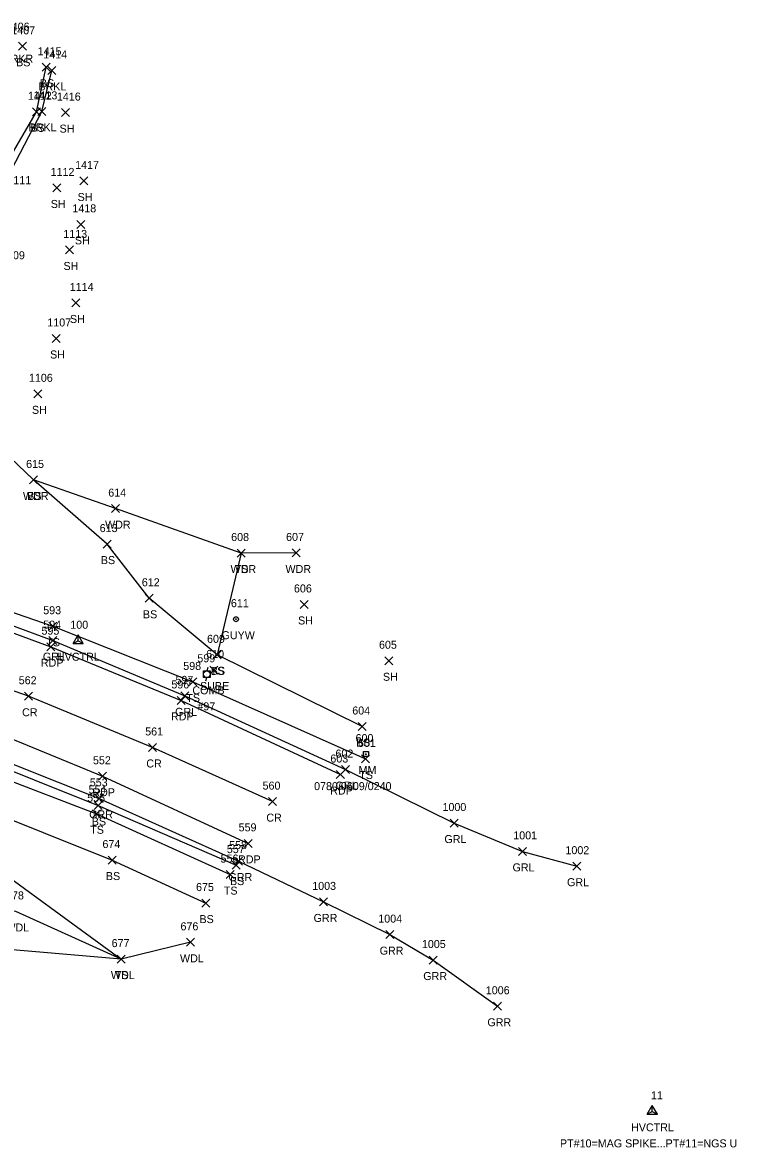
# Model space of a CAD drawing. Extents: x 1485624 to 1495982, y 886445 to 890805.
# Drawn here: x 1495803.4 to 1495981.7, y 890451.8 to 890732.9 of the extents above; entities that cross this region are included whole.
import ezdxf

# ---------------------------------------------------------------- set-up
doc = ezdxf.new("R2010")
doc.units = 0
for name, color, linetype in [('C_A', 7, 'Continuous'), ('C_C', 7, 'Continuous'), ('C_I', 7, 'Continuous'), ('CPSM', 7, 'Continuous'), ('L_A', 7, 'Continuous'), ('L_I', 7, 'Continuous'), ('L_TIC', 7, 'Continuous'), ('LAWA', 7, 'Continuous'), ('LAWE', 7, 'Continuous'), ('LELB', 7, 'Continuous'), ('P_A', 7, 'Continuous'), ('P_I', 7, 'Continuous'), ('P_TIC', 7, 'Continuous'), ('PET', 7, 'Continuous'), ('PRC', 7, 'Continuous'), ('R_A', 7, 'Continuous'), ('R_I', 7, 'Continuous'), ('R_TIC', 7, 'Continuous'), ('RGR', 7, 'Continuous'), ('S_A', 7, 'Continuous'), ('S_C', 7, 'Continuous'), ('S_I', 7, 'Continuous'), ('SRM', 7, 'Continuous'), ('U_A', 7, 'Continuous'), ('U_C', 7, 'Continuous'), ('U_I', 7, 'Continuous'), ('U_TIC', 7, 'Continuous'), ('UP', 7, 'Continuous'), ('UPGW', 7, 'Continuous')]:
    doc.layers.add(name, color=color, linetype=linetype)

msp = doc.modelspace()

# ---------------------------------------------------------------- linework, layer by layer
at = {"layer": 'CPSM'}
for p, q in [((1495816.06, 890577.72), (1495817.31, 890579.88)), ((1495816.06, 890577.72), (1495817.31, 890578.44)), ((1495816.06, 890577.72), (1495818.56, 890577.72)), ((1495818.56, 890577.72), (1495817.31, 890579.88)), ((1495817.31, 890578.44), (1495817.31, 890579.88)), ((1495817.31, 890578.44), (1495817.31, 890578.44)), ((1495817.31, 890578.44), (1495818.56, 890577.72)), ((1495959.45, 890460.14), (1495960.7, 890462.31)), ((1495961.95, 890460.14), (1495960.7, 890462.31)), ((1495960.7, 890460.87), (1495960.7, 890462.31)), ((1495959.45, 890460.14), (1495960.7, 890460.87)), ((1495959.45, 890460.14), (1495961.95, 890460.14)), ((1495960.7, 890460.87), (1495960.7, 890460.87)), ((1495960.7, 890460.87), (1495961.95, 890460.14))]:
    msp.add_line(p, q, dxfattribs=at)
at = {"layer": 'L_TIC'}
for points in [[(1495802.37, 890725.95), (1495804.37, 890727.95)], [(1495804.37, 890725.95), (1495802.37, 890727.95)], [(1495808.31, 890720.72), (1495810.31, 890722.72)], [(1495810.31, 890720.72), (1495808.31, 890722.72)], [(1495809.72, 890719.92), (1495811.72, 890721.92)], [(1495811.72, 890719.92), (1495809.72, 890721.92)], [(1495805.91, 890709.59), (1495807.91, 890711.59)], [(1495807.91, 890709.59), (1495805.91, 890711.59)], [(1495807.27, 890709.7), (1495809.27, 890711.7)], [(1495809.27, 890709.7), (1495807.27, 890711.7)], [(1495813.17, 890709.39), (1495815.17, 890711.39)], [(1495815.17, 890709.39), (1495813.17, 890711.39)], [(1495810.98, 890690.57), (1495812.98, 890692.57)], [(1495812.98, 890690.57), (1495810.98, 890692.57)], [(1495817.68, 890692.31), (1495819.68, 890694.31)], [(1495819.68, 890692.31), (1495817.68, 890694.31)], [(1495816.99, 890681.47), (1495818.99, 890683.47)], [(1495818.99, 890681.47), (1495816.99, 890683.47)], [(1495814.15, 890675.08), (1495816.15, 890677.08)], [(1495816.15, 890675.08), (1495814.15, 890677.08)], [(1495815.76, 890661.84), (1495817.76, 890663.84)], [(1495817.76, 890661.84), (1495815.76, 890663.84)], [(1495810.81, 890652.96), (1495812.81, 890654.96)], [(1495812.81, 890652.96), (1495810.81, 890654.96)], [(1495806.27, 890639.13), (1495808.27, 890641.13)], [(1495808.27, 890639.13), (1495806.27, 890641.13)], [(1495805.15, 890617.61), (1495807.15, 890619.61)], [(1495807.15, 890617.61), (1495805.15, 890619.61)], [(1495805.15, 890617.61), (1495807.15, 890619.61)], [(1495807.15, 890617.61), (1495805.15, 890619.61)], [(1495825.66, 890610.45), (1495827.66, 890612.45)], [(1495827.66, 890610.45), (1495825.66, 890612.45)], [(1495823.52, 890601.59), (1495825.52, 890603.59)], [(1495825.52, 890601.59), (1495823.52, 890603.59)], [(1495857, 890599.35), (1495859, 890601.35)], [(1495859, 890599.35), (1495857, 890601.35)], [(1495857, 890599.35), (1495859, 890601.35)], [(1495859, 890599.35), (1495857, 890601.35)], [(1495870.71, 890599.37), (1495872.71, 890601.37)], [(1495872.71, 890599.37), (1495870.71, 890601.37)], [(1495834.04, 890588.05), (1495836.04, 890590.05)], [(1495836.04, 890588.05), (1495834.04, 890590.05)], [(1495872.75, 890586.51), (1495874.75, 890588.51)], [(1495874.75, 890586.51), (1495872.75, 890588.51)], [(1495809.94, 890581.07), (1495811.94, 890583.07)], [(1495811.94, 890581.07), (1495809.94, 890583.07)], [(1495850.98, 890573.92), (1495852.98, 890575.92)], [(1495852.98, 890573.92), (1495850.98, 890575.92)], [(1495850.98, 890573.92), (1495852.98, 890575.92)], [(1495852.98, 890573.92), (1495850.98, 890575.92)], [(1495893.93, 890572.44), (1495895.93, 890574.44)], [(1495895.93, 890572.44), (1495893.93, 890574.44)], [(1495844.91, 890567.15), (1495846.91, 890569.15)], [(1495846.91, 890567.15), (1495844.91, 890569.15)], [(1495887.25, 890556.01), (1495889.25, 890558.01)], [(1495889.25, 890556.01), (1495887.25, 890558.01)], [(1495888.08, 890547.91), (1495890.08, 890549.91)], [(1495890.08, 890547.91), (1495888.08, 890549.91)], [(1495821.26, 890536.28), (1495823.26, 890538.28)], [(1495823.26, 890536.28), (1495821.26, 890538.28)], [(1495820.91, 890534.22), (1495822.91, 890536.22)], [(1495822.91, 890534.22), (1495820.91, 890536.22)], [(1495824.78, 890522.65), (1495826.78, 890524.65)], [(1495826.78, 890522.65), (1495824.78, 890524.65)], [(1495854.28, 890519.02), (1495856.28, 890521.02)], [(1495856.28, 890519.02), (1495854.28, 890521.02)], [(1495855.79, 890521.39), (1495857.79, 890523.39)], [(1495857.79, 890521.39), (1495855.79, 890523.39)], [(1495848.15, 890511.9), (1495850.15, 890513.9)], [(1495850.15, 890511.9), (1495848.15, 890513.9)], [(1495844.33, 890502.1), (1495846.33, 890504.1)], [(1495846.33, 890502.1), (1495844.33, 890504.1)], [(1495827.07, 890497.9), (1495829.07, 890499.9)], [(1495829.07, 890497.9), (1495827.07, 890499.9)], [(1495827.07, 890497.9), (1495829.07, 890499.9)], [(1495829.07, 890497.9), (1495827.07, 890499.9)]]:
    msp.add_lwpolyline(points, dxfattribs=at)
at = {"layer": 'LAWA'}
for points in [[(1495871.71, 890600.37), (1495858, 890600.35), (1495826.66, 890611.45), (1495806.15, 890618.61), (1495786.69, 890637.23), (1495776.7, 890630.96), (1495766.77, 890633.56), (1495731.4, 890630.07), (1495727.41, 890643.49), (1495711.78, 890647.37), (1495680.11, 890664.79)], [(1495845.33, 890503.1), (1495828.07, 890498.9), (1495801.7, 890510.81), (1495780.01, 890514.68), (1495754.98, 890512.53), (1495737.5, 890505.74), (1495734.75, 890491.63)]]:
    msp.add_lwpolyline(points, dxfattribs=at)
at = {"layer": 'LAWE'}
msp.add_lwpolyline([(1495794.56, 890691.15), (1495799.61, 890694.04), (1495808.27, 890710.7), (1495810.72, 890720.92)], dxfattribs=at)
at = {"layer": 'LELB'}
for points in [[(1495793.44, 890691.24), (1495797.73, 890694.96), (1495806.91, 890710.59), (1495809.31, 890721.72)], [(1495617.51, 890647.42), (1495659.25, 890631.91), (1495662.58, 890630.34), (1495680.12, 890623), (1495718.11, 890611.07), (1495750.98, 890602.51), (1495783.18, 890591.68), (1495810.94, 890582.07), (1495845.91, 890568.15), (1495889.08, 890548.91)], [(1495888.25, 890557.01), (1495851.98, 890574.92), (1495835.04, 890589.05), (1495824.52, 890602.59), (1495806.15, 890618.61)], [(1495858, 890600.35), (1495851.98, 890574.92)], [(1495643.24, 890569.95), (1495650.54, 890577.25), (1495664.27, 890582.53), (1495690.14, 890577.82), (1495701.7, 890574.71), (1495732.13, 890567.79), (1495761.45, 890557.4), (1495788.87, 890547.86), (1495821.91, 890535.22), (1495855.28, 890520.02)], [(1495702.25, 890576.45), (1495732.13, 890567.79), (1495762.2, 890558.81), (1495790.25, 890550.14), (1495822.26, 890537.28), (1495856.79, 890522.39)], [(1495764.59, 890546.09), (1495791.26, 890537.44), (1495825.78, 890523.65), (1495849.15, 890512.9)], [(1495757.57, 890537.9), (1495788.35, 890527.83), (1495828.07, 890498.9), (1495795.98, 890501.66), (1495778.3, 890500.66), (1495774.03, 890506.35), (1495756.49, 890501.63), (1495740.74, 890489.73)]]:
    msp.add_lwpolyline(points, dxfattribs=at)
at = {"layer": 'P_TIC'}
for points in [[(1495809.5, 890575.96), (1495811.5, 890577.96)], [(1495811.5, 890575.96), (1495809.5, 890577.96)], [(1495803.87, 890563.57), (1495805.87, 890565.57)], [(1495805.87, 890563.57), (1495803.87, 890565.57)], [(1495842, 890562.53), (1495844, 890564.53)], [(1495844, 890562.53), (1495842, 890564.53)], [(1495834.89, 890550.78), (1495836.89, 890552.78)], [(1495836.89, 890550.78), (1495834.89, 890552.78)], [(1495822.36, 890543.58), (1495824.36, 890545.58)], [(1495824.36, 890543.58), (1495822.36, 890545.58)], [(1495881.78, 890544.01), (1495883.78, 890546.01)], [(1495883.78, 890544.01), (1495881.78, 890546.01)], [(1495864.85, 890537.25), (1495866.85, 890539.25)], [(1495866.85, 890537.25), (1495864.85, 890539.25)], [(1495858.75, 890526.82), (1495860.75, 890528.82)], [(1495860.75, 890526.82), (1495858.75, 890528.82)]]:
    msp.add_lwpolyline(points, dxfattribs=at)
at = {"layer": 'PET'}
for points in [[(1495609.58, 890624.88), (1495650.02, 890621.06), (1495682.45, 890614.6), (1495716.9, 890606.52), (1495749.59, 890597.76), (1495779.95, 890588.14), (1495810.5, 890576.96), (1495843, 890563.53), (1495882.78, 890545.01)], [(1495611.34, 890596.8), (1495660.14, 890590.36), (1495685.99, 890587.32), (1495704.29, 890583.39), (1495734.68, 890576.01), (1495763.96, 890566.85), (1495794.17, 890556.56), (1495823.36, 890544.58), (1495859.75, 890527.82)]]:
    msp.add_lwpolyline(points, dxfattribs=at)
at = {"layer": 'PRC'}
msp.add_lwpolyline([(1495865.85, 890538.25), (1495835.89, 890551.78), (1495804.87, 890564.57), (1495770.54, 890576.59), (1495737.23, 890586.26), (1495702.08, 890594.9), (1495658.63, 890603.44), (1495614.66, 890611.01)], dxfattribs=at)
at = {"layer": 'R_TIC'}
for points in [[(1495809.95, 890577.47), (1495811.95, 890579.47)], [(1495811.95, 890577.47), (1495809.95, 890579.47)], [(1495842.97, 890563.67), (1495844.97, 890565.67)], [(1495844.97, 890563.67), (1495842.97, 890565.67)], [(1495883.04, 890545.25), (1495885.04, 890547.25)], [(1495885.04, 890545.25), (1495883.04, 890547.25)], [(1495821.57, 890538.06), (1495823.57, 890540.06)], [(1495823.57, 890538.06), (1495821.57, 890540.06)], [(1495910.23, 890531.9), (1495912.23, 890533.9)], [(1495912.23, 890531.9), (1495910.23, 890533.9)], [(1495927.25, 890524.82), (1495929.25, 890526.82)], [(1495929.25, 890524.82), (1495927.25, 890526.82)], [(1495856.36, 890522.4), (1495858.36, 890524.4)], [(1495858.36, 890522.4), (1495856.36, 890524.4)], [(1495940.85, 890521.12), (1495942.85, 890523.12)], [(1495942.85, 890521.12), (1495940.85, 890523.12)], [(1495877.61, 890512.19), (1495879.61, 890514.19)], [(1495879.61, 890512.19), (1495877.61, 890514.19)], [(1495894.11, 890504.02), (1495896.11, 890506.02)], [(1495896.11, 890504.02), (1495894.11, 890506.02)], [(1495905, 890497.67), (1495907, 890499.67)], [(1495907, 890497.67), (1495905, 890499.67)], [(1495921.02, 890486.12), (1495923.02, 890488.12)], [(1495923.02, 890486.12), (1495921.02, 890488.12)]]:
    msp.add_lwpolyline(points, dxfattribs=at)
at = {"layer": 'RGR'}
for points in [[(1495657.99, 890625.64), (1495670.77, 890620.07), (1495682.61, 890616.63), (1495717.55, 890608.37), (1495750.4, 890599.5), (1495781.03, 890589.57), (1495810.95, 890578.47), (1495843.97, 890564.67), (1495884.04, 890546.25), (1495911.23, 890532.9), (1495928.25, 890525.82), (1495941.85, 890522.12)], [(1495664.27, 890582.53), (1495685.11, 890581.37), (1495702.59, 890578.48), (1495733.01, 890569.82), (1495762.5, 890560.97), (1495791.3, 890551.45), (1495822.57, 890539.06), (1495857.36, 890523.4), (1495878.61, 890513.19), (1495895.11, 890505.02), (1495906, 890498.67), (1495922.02, 890487.12)]]:
    msp.add_lwpolyline(points, dxfattribs=at)
at = {"layer": 'SRM'}
msp.add_lwpolyline([(1495888.53, 890550.75), (1495889.78, 890550.75), (1495889.78, 890549.5), (1495888.53, 890549.5)], close=True, dxfattribs=at)
msp.add_circle((1495889.16, 890550.12), 0.0833, dxfattribs=at)
at = {"layer": 'U_TIC'}
for points in [[(1495850.21, 890570.13), (1495852.21, 890572.13)], [(1495852.21, 890570.13), (1495850.21, 890572.13)]]:
    msp.add_lwpolyline(points, dxfattribs=at)
at = {"layer": 'UP'}
for p, q in [((1495849.69, 890571.73), (1495849.44, 890570.9)), ((1495848.61, 890569.23), (1495848.61, 890570.9)), ((1495848.61, 890570.9), (1495850.27, 890570.9)), ((1495850.27, 890569.23), (1495848.61, 890569.23)), ((1495849.19, 890568.4), (1495849.44, 890569.23)), ((1495849.44, 890570.06), (1495849.44, 890570.06)), ((1495850.27, 890570.9), (1495850.27, 890569.23))]:
    msp.add_line(p, q, dxfattribs=at)
msp.add_circle((1495849.44, 890570.06), 0.833, dxfattribs=at)
at = {"layer": 'UPGW'}
for radius in [0.625, 0.0833]:
    msp.add_circle((1495856.72, 890583.83), radius, dxfattribs=at)

# ---------------------------------------------------------------- texts
at = {"layer": 'C_A'}
for p in [(1495812, 890573.44), (1495955.39, 890455.87)]:
    msp.add_text('HVCTRL', height=2, dxfattribs=at).set_placement(p)
at = {"layer": 'C_C'}
msp.add_text('PT#10=MAG SPIKE...PT#11=NGS U', height=2, dxfattribs=at).set_placement((1495937.63, 890451.87))
at = {"layer": 'C_I'}
for s, p in [('100', (1495815.35, 890581.44)), ('11', (1495960.37, 890463.87))]:
    msp.add_text(s, height=2, dxfattribs=at).set_placement(p)
at = {"layer": 'L_A'}
for s, p in [('BRKR', (1495798.64, 890722.87)), ('BS', (1495801.81, 890721.95)), ('BRKL', (1495807.36, 890715.92)), ('BS', (1495807.75, 890716.72)), ('BRKL', (1495804.92, 890705.7)), ('BS', (1495805.35, 890705.59)), ('SH', (1495812.66, 890705.39)), ('SH', (1495817.17, 890688.31)), ('SH', (1495810.47, 890686.57)), ('SH', (1495816.48, 890677.47)), ('SH', (1495813.64, 890671.08)), ('SH', (1495815.25, 890657.84)), ('SH', (1495810.29, 890648.96)), ('SH', (1495805.76, 890635.13)), ('WDR', (1495803.52, 890613.61)), ('BS', (1495804.59, 890613.61)), ('WDR', (1495824.02, 890606.45)), ('BS', (1495822.96, 890597.59)), ('WDR', (1495855.36, 890595.35)), ('TS', (1495856.41, 890595.35)), ('WDR', (1495869.08, 890595.37)), ('BS', (1495833.48, 890584.05)), ('SH', (1495872.23, 890582.51)), ('TS', (1495809.35, 890577.07)), ('TS', (1495850.39, 890569.92)), ('BS', (1495850.43, 890569.92)), ('SH', (1495893.42, 890568.44)), ('TS', (1495844.32, 890563.15)), ('BS', (1495886.69, 890552.01)), ('TS', (1495887.49, 890543.91)), ('TS', (1495820.32, 890530.22)), ('BS', (1495820.7, 890532.28)), ('BS', (1495824.22, 890518.65)), ('BS', (1495855.23, 890517.39)), ('TS', (1495853.69, 890515.02)), ('BS', (1495847.59, 890507.9)), ('WDL', (1495799.12, 890505.81)), ('WDL', (1495842.74, 890498.1)), ('WDL', (1495825.48, 890493.9)), ('TS', (1495826.48, 890493.9))]:
    msp.add_text(s, height=2, dxfattribs=at).set_placement(p)
at = {"layer": 'L_I'}
for s, p in [('1406', (1495799.23, 890730.87)), ('1407', (1495800.6, 890729.95)), ('1415', (1495807.19, 890724.72)), ('1414', (1495808.59, 890723.92)), ('1412', (1495804.78, 890713.59)), ('1413', (1495806.15, 890713.7)), ('1416', (1495811.99, 890713.39)), ('1417', (1495816.55, 890696.31)), ('1112', (1495810.42, 890694.57)), ('1111', (1495799.62, 890692.51)), ('1418', (1495815.86, 890685.47)), ('1113', (1495813.59, 890679.08)), ('1109', (1495798.04, 890673.75)), ('1114', (1495815.2, 890665.84)), ('1107', (1495809.6, 890656.96)), ('1106', (1495805.01, 890643.13)), ('615', (1495804.31, 890621.61)), ('615', (1495804.31, 890621.61)), ('614', (1495824.82, 890614.45)), ('613', (1495822.68, 890605.59)), ('608', (1495855.51, 890603.35)), ('608', (1495855.51, 890603.35)), ('607', (1495869.23, 890603.37)), ('612', (1495833.2, 890592.05)), ('606', (1495871.2, 890590.51)), ('593', (1495808.58, 890585.07)), ('609', (1495849.49, 890577.92)), ('609', (1495849.49, 890577.92)), ('605', (1495892.44, 890576.44)), ('598', (1495843.55, 890571.15)), ('604', (1495885.76, 890560.01)), ('601', (1495887.16, 890551.91)), ('554', (1495819.9, 890540.28)), ('555', (1495819.55, 890538.22)), ('674', (1495823.37, 890526.65)), ('557', (1495854.43, 890525.39)), ('556', (1495852.87, 890523.02)), ('678', (1495799.29, 890513.81)), ('675', (1495846.74, 890515.9)), ('676', (1495842.86, 890506.1)), ('677', (1495825.66, 890501.9)), ('677', (1495825.66, 890501.9))]:
    msp.add_text(s, height=2, dxfattribs=at).set_placement(p)
at = {"layer": 'P_A'}
for s, p in [('RDP', (1495807.99, 890571.96)), ('CR', (1495803.3, 890559.57)), ('RDP', (1495840.48, 890558.53)), ('CR', (1495834.32, 890546.78)), ('RDP', (1495820.85, 890539.58)), ('RDP', (1495880.26, 890540.01)), ('CR', (1495864.29, 890533.25)), ('RDP', (1495857.24, 890522.82))]:
    msp.add_text(s, height=2, dxfattribs=at).set_placement(p)
at = {"layer": 'P_I'}
for s, p in [('595', (1495808.14, 890579.96)), ('562', (1495802.46, 890567.57)), ('596', (1495840.58, 890566.53)), ('561', (1495834.04, 890554.78)), ('552', (1495821, 890547.58)), ('603', (1495880.29, 890548.01)), ('560', (1495863.36, 890541.25)), ('559', (1495857.38, 890530.82))]:
    msp.add_text(s, height=2, dxfattribs=at).set_placement(p)
at = {"layer": 'R_A'}
for s, p in [('GRL', (1495808.49, 890573.47)), ('GRL', (1495841.51, 890559.67)), ('GRL', (1495881.59, 890541.25)), ('GRR', (1495820.06, 890534.06)), ('GRL', (1495908.77, 890527.9)), ('GRL', (1495925.79, 890520.82)), ('GRR', (1495854.85, 890518.4)), ('GRL', (1495939.39, 890517.12)), ('GRR', (1495876.1, 890508.19)), ('GRR', (1495892.6, 890500.02)), ('GRR', (1495903.49, 890493.67)), ('GRR', (1495919.51, 890482.12))]:
    msp.add_text(s, height=2, dxfattribs=at).set_placement(p)
at = {"layer": 'R_I'}
for s, p in [('594', (1495808.59, 890581.47)), ('597', (1495841.61, 890567.67)), ('602', (1495881.56, 890549.25)), ('553', (1495820.21, 890542.06)), ('1000', (1495908.29, 890535.9)), ('1001', (1495925.97, 890528.82)), ('558', (1495855, 890526.4)), ('1002', (1495939, 890525.12)), ('1003', (1495875.76, 890516.19)), ('1004', (1495892.26, 890508.02)), ('1005', (1495903.15, 890501.67)), ('1006', (1495919.11, 890490.12))]:
    msp.add_text(s, height=2, dxfattribs=at).set_placement(p)
at = {"layer": 'S_A'}
msp.add_text('MM', height=2, dxfattribs=at).set_placement((1495887.34, 890545.12))
at = {"layer": 'S_C'}
msp.add_text('0780/0609/0240', height=2, dxfattribs=at).set_placement((1495876.23, 890541.12))
at = {"layer": 'S_I'}
msp.add_text('600', height=2, dxfattribs=at).set_placement((1495886.58, 890553.12))
at = {"layer": 'U_A'}
for s, p in [('GUYW', (1495853.12, 890578.83)), ('COMB', (1495845.83, 890565.06)), ('SUBE', (1495847.74, 890566.13))]:
    msp.add_text(s, height=2, dxfattribs=at).set_placement(p)
at = {"layer": 'U_C'}
msp.add_text('#97', height=2, dxfattribs=at).set_placement((1495847.08, 890561.06))
at = {"layer": 'U_I'}
for s, p in [('611', (1495855.45, 890586.83)), ('599', (1495847.07, 890573.06)), ('610', (1495849.28, 890574.13))]:
    msp.add_text(s, height=2, dxfattribs=at).set_placement(p)

doc.saveas('drawing.dxf')
